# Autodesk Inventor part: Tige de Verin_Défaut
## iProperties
Shininess: 64.0
Length Units: 11269
Angle Units: 11279
Time Units: 11290
Mass Units: 11283
Length Display Precision: 3
Angle Display Precision: 2
Compacted: True
Part Number: Tige de Verin_Défaut
Document SubType Name: Modeling
Created: 2006-11
Material: Par défaut
Designer: profs_sti
Density: 0.0
Volumn: 0.0
Area: 0.0
PropertySet Name: Model Information
Control State: 0
Master: False
Checked Out: False
Author: profs_sti
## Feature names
1. Base1
